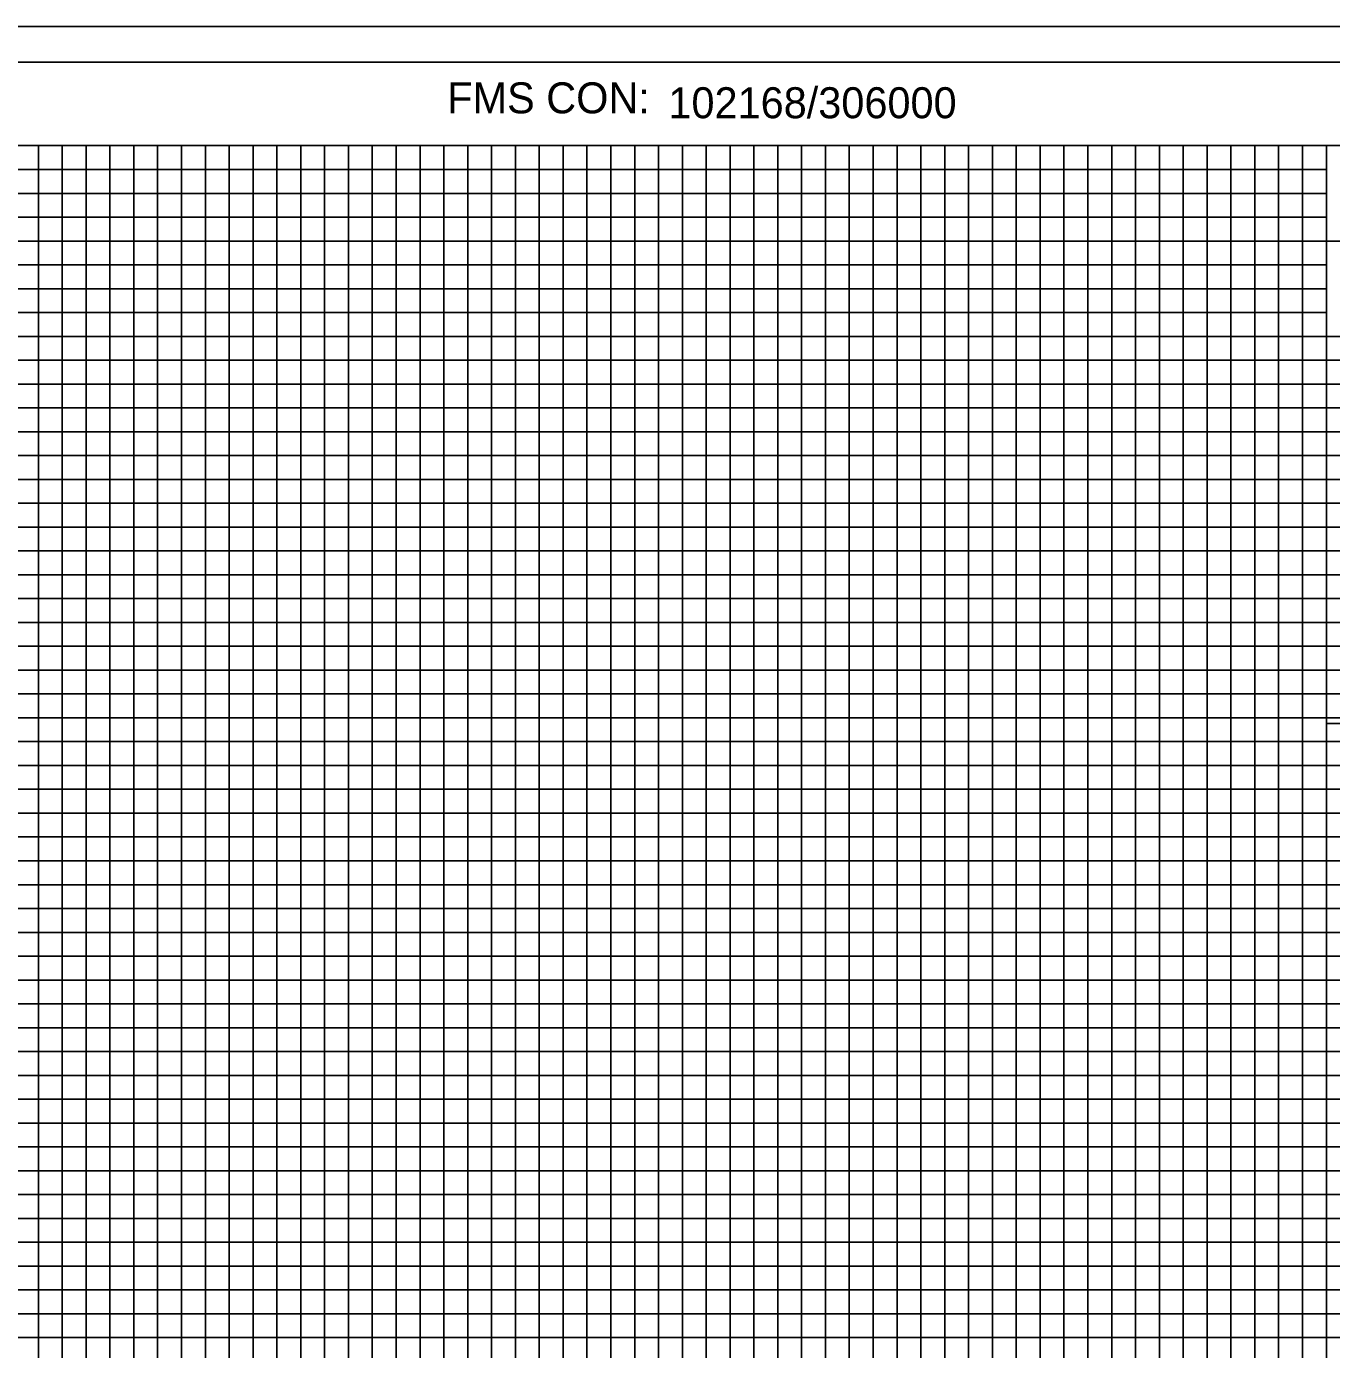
# Model space of a CAD drawing. Extents: x -10 to 342, y -5 to 215.
# Drawn here: x 258.5 to 313.2, y 159.5 to 215 of the extents above; entities that cross this region are included whole.
import ezdxf

# ---------------------------------------------------------------- set-up
doc = ezdxf.new("R2010")
doc.units = 0
for name, color, linetype in [('SHEET_BORDER', 7, 'Continuous'), ('SHEET_BORDER_TX', 7, 'Continuous'), ('SHEET_LOGO', 7, 'Continuous'), ('SHEET_PLOTTING_SHAPE', 7, 'Continuous'), ('SHEET_PRELIM', 7, 'Continuous'), ('SHEET_PROJ_NUMBER', 7, 'Continuous'), ('XS_SHEET_MAJOR_GRIDS', 7, 'Continuous'), ('XS_SHEET_MEDIUM_GRIDS', 7, 'Continuous'), ('XS_SHEET_MINOR_GRIDS', 7, 'Continuous')]:
    doc.layers.add(name, color=color, linetype=linetype)

msp = doc.modelspace()

# ---------------------------------------------------------------- linework, layer by layer
at = {"layer": 'SHEET_BORDER'}
for p, q in [((-9.8, 213.5), (342.2, 213.5)), ((5, 210), (340, 210)), ((313, 206), (340, 206))]:
    msp.add_line(p, q, dxfattribs=at)
at = {"layer": 'SHEET_LOGO'}
msp.add_lwpolyline([(313, 185.757), (329.243, 185.757), (329.243, 202), (313, 202)], close=True, dxfattribs=at)
at = {"layer": 'SHEET_PLOTTING_SHAPE'}
msp.add_lwpolyline([(-3.8, -5), (342.2, -5), (342.2, 215), (-3.8, 215)], close=True, dxfattribs=at)
at = {"layer": 'SHEET_PRELIM'}
msp.add_lwpolyline([(313, 185.757), (329.243, 185.757), (329.243, 202), (313, 202)], close=True, dxfattribs=at)
at = {"layer": 'SHEET_PROJ_NUMBER'}
for q in [(313, 210), (340, 202)]:
    msp.add_line((313, 202), q, dxfattribs=at)
at = {"layer": 'XS_SHEET_MAJOR_GRIDS'}
for p, q in [((260, 0), (260, 210)), ((270, 0), (270, 210)), ((280, 0), (280, 210)), ((290, 0), (290, 210)), ((300, 0), (300, 210)), ((310, 0), (310, 210)), ((5, 200), (340, 200)), ((5, 190), (340, 190)), ((5, 180), (340, 180)), ((5, 170), (340, 170)), ((5, 160), (340, 160))]:
    msp.add_line(p, q, dxfattribs=at)
at = {"layer": 'XS_SHEET_MEDIUM_GRIDS'}
for p, q in [((265, 0), (265, 210)), ((275, 0), (275, 210)), ((285, 0), (285, 210)), ((295, 0), (295, 210)), ((305, 0), (305, 210)), ((5, 205), (313, 205)), ((5, 195), (340, 195)), ((5, 185), (340, 185)), ((5, 175), (340, 175)), ((5, 165), (340, 165))]:
    msp.add_line(p, q, dxfattribs=at)
at = {"layer": 'XS_SHEET_MINOR_GRIDS'}
for p, q in [((259, 0), (259, 210)), ((261, 0), (261, 210)), ((262, 0), (262, 210)), ((263, 0), (263, 210)), ((264, 0), (264, 210)), ((266, 0), (266, 210)), ((267, 0), (267, 210)), ((268, 0), (268, 210)), ((269, 0), (269, 210)), ((271, 0), (271, 210)), ((272, 0), (272, 210)), ((273, 0), (273, 210)), ((274, 0), (274, 210)), ((276, 0), (276, 210)), ((277, 0), (277, 210)), ((278, 0), (278, 210)), ((279, 0), (279, 210)), ((281, 0), (281, 210)), ((282, 0), (282, 210)), ((283, 0), (283, 210)), ((284, 0), (284, 210)), ((286, 0), (286, 210)), ((287, 0), (287, 210)), ((288, 0), (288, 210)), ((289, 0), (289, 210)), ((291, 0), (291, 210)), ((292, 0), (292, 210)), ((293, 0), (293, 210)), ((294, 0), (294, 210)), ((296, 0), (296, 210)), ((297, 0), (297, 210)), ((298, 0), (298, 210)), ((299, 0), (299, 210)), ((301, 0), (301, 210)), ((302, 0), (302, 210)), ((303, 0), (303, 210)), ((304, 0), (304, 210)), ((306, 0), (306, 210)), ((307, 0), (307, 210)), ((308, 0), (308, 210)), ((309, 0), (309, 210)), ((311, 0), (311, 210)), ((312, 0), (312, 210)), ((5, 209), (313, 209)), ((5, 208), (313, 208)), ((5, 207), (313, 207)), ((5, 206), (313, 206)), ((5, 204), (313, 204)), ((5, 203), (313, 203)), ((5, 202), (313, 202)), ((313, 0), (313, 202)), ((5, 201), (340, 201)), ((5, 199), (340, 199)), ((5, 198), (340, 198)), ((5, 197), (340, 197)), ((5, 196), (340, 196)), ((5, 194), (340, 194)), ((5, 193), (340, 193)), ((5, 192), (340, 192)), ((5, 191), (340, 191)), ((5, 189), (340, 189)), ((5, 188), (340, 188)), ((5, 187), (340, 187)), ((5, 186), (340, 186)), ((5, 184), (340, 184)), ((5, 183), (340, 183)), ((5, 182), (340, 182)), ((5, 181), (340, 181)), ((5, 179), (340, 179)), ((5, 178), (340, 178)), ((5, 177), (340, 177)), ((5, 176), (340, 176)), ((5, 174), (340, 174)), ((5, 173), (340, 173)), ((5, 172), (340, 172)), ((5, 171), (340, 171)), ((5, 169), (340, 169)), ((5, 168), (340, 168)), ((5, 167), (340, 167)), ((5, 166), (340, 166)), ((5, 164), (340, 164)), ((5, 163), (340, 163)), ((5, 162), (340, 162)), ((5, 161), (340, 161))]:
    msp.add_line(p, q, dxfattribs=at)

# ---------------------------------------------------------------- texts
at = {"layer": 'SHEET_BORDER_TX'}
for s, height, p in [('FMS CON:', 1.3, (276.14, 211.355)), ('102168/306000', 1.30002, (285.414, 211.15))]:
    msp.add_text(s, height=height, rotation=360, dxfattribs=at).set_placement(p)

doc.saveas('drawing.dxf')
